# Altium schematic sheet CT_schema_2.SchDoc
size 229 x 200 mm
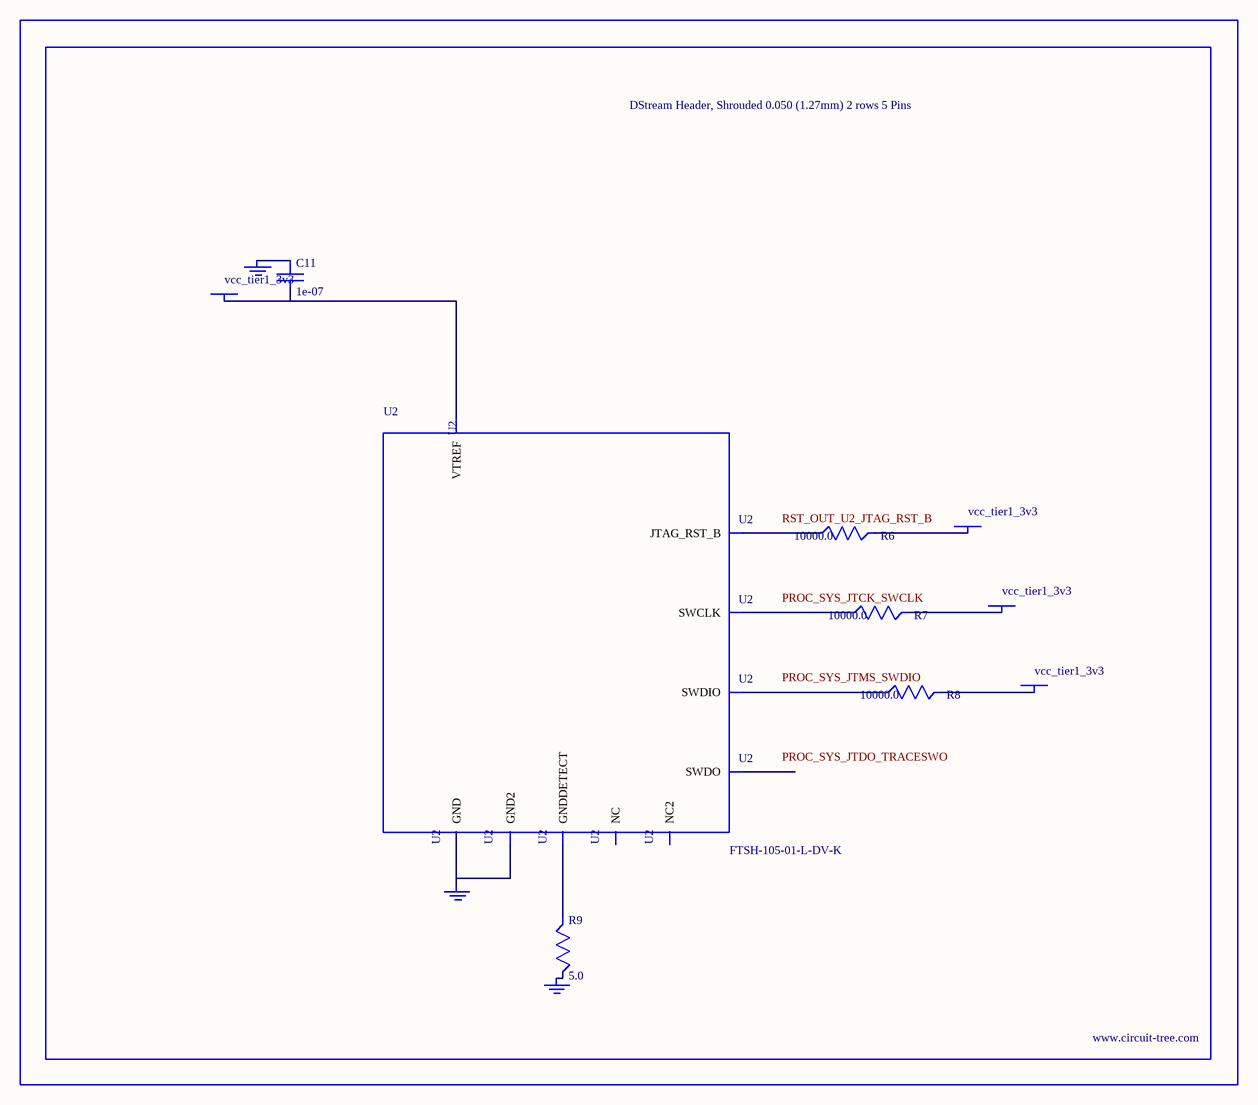
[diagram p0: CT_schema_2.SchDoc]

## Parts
BORDER1  (no value)
C11  1e-07  [C0402]
GND_INSTANCE_1_0  (no value)
GND_INSTANCE_1_1  (no value)
GND_INSTANCE_1_2  (no value)
POWER_INSTANCE_1_0  vcc_tier1_3v3
POWER_INSTANCE_1_1  vcc_tier1_3v3
POWER_INSTANCE_1_2  vcc_tier1_3v3
POWER_INSTANCE_1_3  vcc_tier1_3v3
R6  10000.0  [R0603]
R7  10000.0  [R0603]
R8  10000.0  [R0603]
R9  5.0  [R0603]
U2  FTSH-105-01-L-DV-K  [SAMTEC_FTSH-105-01-L-DV-K]

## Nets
NetC11_1: C11.1 GND_INSTANCE_1_0.0(GND)
NetC11_2: C11.2 POWER_INSTANCE_1_0.0(PWR) U2.1(VTREF)
NetGND_INSTANCE_1_1_0: GND_INSTANCE_1_1.0(GND) R9.2
NetGND_INSTANCE_1_2_0: GND_INSTANCE_1_2.0(GND) U2.3(GND) U2.5(GND2)
NetPOWER_INSTANCE_1_1_0: POWER_INSTANCE_1_1.0(PWR) R8.2
NetPOWER_INSTANCE_1_2_0: POWER_INSTANCE_1_2.0(PWR) R7.2
NetPOWER_INSTANCE_1_3_0: POWER_INSTANCE_1_3.0(PWR) R6.2
NetR6_1: R6.1 U2.10(JTAG_RST_B)
NetR7_1: R7.1 U2.4(SWCLK)
NetR8_1: R8.1 U2.2(SWDIO)
NetR9_1: R9.1 U2.9(GNDDETECT)

Not connected (* = marked no-connect by the designer): U2 6(SWDO) 7(NC) 8(NC2)

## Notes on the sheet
- Labels drawn without touching a wire or pin: PROC_SYS_JTCK_SWCLK, PROC_SYS_JTDO_TRACESWO, PROC_SYS_JTMS_SWDIO, RST_OUT_U2_JTAG_RST_B

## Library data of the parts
BORDER1 = BORDER_PAGE1
C11 = C0402C104K3RACTU
GND_INSTANCE_1_0-GND_INSTANCE_1_2 = GND
POWER_INSTANCE_1_0-POWER_INSTANCE_1_3 = PWR
R6-R8 = RC0603JR-0710KL
R9 = ERJ-3GEYJ5R1V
